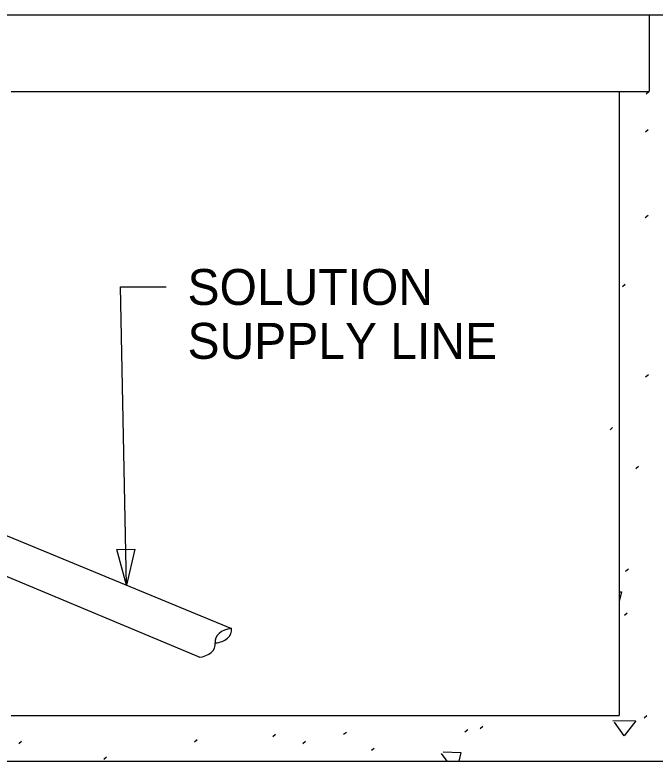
# Model space of a CAD drawing. Extents: x 3239 to 4230, y -4276 to -2494.
# Drawn here: x 3679.6 to 3733.1, y -3454.8 to -3392.5 of the extents above; entities that cross this region are included whole.
import ezdxf

# ---------------------------------------------------------------- set-up
doc = ezdxf.new("R2010")
doc.units = 0
doc.layers.add('2', color=7, linetype='Continuous')

msp = doc.modelspace()

# ---------------------------------------------------------------- linework, layer by layer
at = {"layer": '2'}
for p, q in [((3676.79, -3392.515), (3732.59, -3392.515)), ((3732.59, -3392.515), (3737.69, -3392.515)), ((3732.59, -3392.515), (3732.59, -3397.615)), ((3584.929, -3397.191), (3697.703, -3443.758)), ((3732.59, -3397.615), (3732.59, -3398.915)), ((3679.29, -3398.915), (3730.09, -3398.915)), ((3730.09, -3398.915), (3732.59, -3398.915)), ((3730.09, -3398.915), (3730.09, -3451.015)), ((3732.337, -3399.102), (3732.57, -3398.916)), ((3583.873, -3399.72), (3695.049, -3446.137)), ((3732.291, -3402.271), (3732.524, -3402.085)), ((3732.274, -3409.421), (3732.507, -3409.234)), ((3730.36, -3415.184), (3730.593, -3414.998)), ((3732.297, -3422.724), (3732.53, -3422.537)), ((3729.35, -3427.151), (3729.536, -3426.965)), ((3731.482, -3430.389), (3731.715, -3430.202)), ((3730.629, -3438.948), (3730.862, -3438.761)), ((3730.536, -3442.629), (3730.769, -3442.442)), ((3679.29, -3451.015), (3730.09, -3451.015)), ((3732.167, -3451.202), (3732.4, -3451.016)), ((3718.468, -3452.088), (3718.701, -3451.901)), ((3701.16, -3452.766), (3701.393, -3452.58)), ((3707.075, -3452.577), (3707.308, -3452.391)), ((3717.21, -3452.367), (3717.443, -3452.181)), ((3679.93, -3453.351), (3680.163, -3453.165)), ((3694.613, -3453.209), (3694.846, -3453.022)), ((3703.664, -3453.35), (3703.897, -3453.164)), ((3709.401, -3453.914), (3709.634, -3453.728)), ((3687.035, -3454.66), (3687.268, -3454.474)), ((3675.49, -3454.815), (3733.89, -3454.815))]:
    msp.add_line(p, q, dxfattribs=at)
for points in [[(3688.926, -3440.134), (3688.425, -3415.23), (3692.255, -3415.23)], [(3730.09, -3440.678), (3730.275, -3440.687), (3730.09, -3441.485)], [(3729.564, -3451.435), (3731.498, -3451.458), (3730.519, -3452.717), (3729.704, -3451.575)], [(3715.723, -3454.815), (3715.248, -3454.176)], [(3715.388, -3454.037), (3716.856, -3454.106), (3716.691, -3454.815)]]:
    msp.add_lwpolyline(points, dxfattribs=at)
msp.add_lwpolyline([(3689.615, -3437.12), (3688.926, -3440.134), (3688.116, -3437.15)], close=True, dxfattribs=at)
for centre, major_axis, start_param, end_param in [((3697.865, -3444.835), (1.53, 0), 1.677447, 3.248243), ((3696.181, -3443.874), (1.53, 0), 4.819039, 6.389836), ((3694.823, -3445.066), (-1.53, 0), 1.677447, 3.248243)]:
    msp.add_ellipse(centre, major_axis=major_axis, ratio=0.707981, start_param=start_param, end_param=end_param, dxfattribs=at)

# ---------------------------------------------------------------- texts
for s, p in [('SOLUTION', (3694.03, -3416.73)), ('SUPPLY LINE', (3694.03, -3421.23))]:
    msp.add_text(s, height=3, dxfattribs=at).set_placement(p)

doc.saveas('drawing.dxf')
